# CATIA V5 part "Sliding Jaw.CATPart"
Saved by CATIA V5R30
Part number: Sliding Jaw
Bounding box of the stored display mesh (mm): x -32 to 32, y -16 to 16, z -9 to 36
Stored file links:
  D:\PROJECTS\CATIA V56R 2020\Resources\Parts File\c12_catia_v5_6r2020_prt\c12_catia_v5-6r2020 figr_12-19\Sliding Jaw.CATPart
  C:\Program Files\Dassault Systemes\B09\intel_a\reffiles\standard\MetricThickPitch.txt
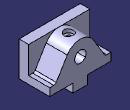
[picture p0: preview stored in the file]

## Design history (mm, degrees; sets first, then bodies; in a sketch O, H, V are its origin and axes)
Body1 (main body)
  Sketch1 on xy-plane, origin (0, 0, 0), H (1, 0, 0), V (0, 1, 0)
    line L1 (-32, -16) -> (32, -16)
    line L2 (32, -16) -> (32, 16)
    line L3 (32, 16) -> (-32, 16)
    line L4 (-32, 16) -> (-32, -16)
    distance H L1 = 16
    distance V L4 = 32
    length L4 = 32
    length L1 = 64
    horizontal: L1 H, L3 H
    vertical: L2 V, L4 V
  Pad1: profile Sketch1, direction (0, 0, 1), length 8
  Sketch2 on face of Pad1, origin (0, -16, 0), H (1, 0, 0), V (0, 0, 1)
    point P1 (-32, 0)
    line L1 (-32, 0) -> (32, 0)
    line L2 (32, 0) -> (32, 36)
    line L3 (32, 36) -> (-32, 36)
    line L4 (-32, 36) -> (-32, 0)
    reference projected line E1 (32, 0) -> (32, 8) from edge of Pad1
    reference projected line E2 (-32, 8) -> (-32, 0) from edge of Pad1
    length L2 = 36
    coincidence: P1 H, L2 E1, L4 E2
    horizontal: L1 H, L3 H
    vertical: L2 V, L4 V
  Pad2: profile Sketch2, direction (0, 1, 0), length 10
  Sketch3 on face of Pad1, origin (0, 16, 0), H (-1, 0, 0), V (0, 0, 1)
    arc A1 centre (0, 20) radius 16 from (13.6777, 28.3018) to (-13.6777, 28.3018) ccw
    point P1 (0, 20)
    reference projected line E1 (-32, 36) -> (32, 36) from edge of Pad2
    line L1 (-26, 8) -> (-13.6777, 28.3018)
    point P2 (-26, 8)
    line L2 (13.6777, 28.3018) -> (26, 8)
    point P3 (26, 8)
    reference projected line E2 (32, 8) -> (-32, 8) from edge of Pad1
    reference projected line E3 (32, 8) -> (-32, 8) from edge of Pad1
    line L3 (-26, 8) -> (26, 8)
    radius A1 = 16
    length L3 = 52
    distance V P3 = 26
    coincidence: P1 V, E2 P2, E3 P3
    tangency: A1 E1, L2 A1, L1 A1
    horizontal: L3 H
  Pad3: profile Sketch3, direction (0, -1, 0), up to the existing solid (limit type 2)
  Fillet1: radius 3, on 2 edges
  Sketch4 on face of Pad1, origin (-2.6964, 16, 22.8197), H (1, 0, 0), V (0, 0, -1)
    point P1 (2.6964, 2.8197)
    reference projected arc E1 centre (2.6964, 2.8197) radius 16 from (-10.9814, -5.4821) to (16.3741, -5.4821) ccw from edge of Pad3
    concentricity: P1 E1
  Hole1: placed by Sketch4, at (0, 16, 20) direction (0, -1, 0), diameter 12, depth 22, V-bottom angle 120
  Sketch5 on face of Pad1, origin (0, 16, 0), H (-1, 0, 0), V (0, 0, 1)
    point P1 (-7.75, 0)
    line L1 (-7.75, 0) -> (7.75, 0)
    line L2 (7.75, 0) -> (7.75, -9)
    line L3 (7.75, -9) -> (-7.75, -9)
    line L4 (-7.75, -9) -> (-7.75, 0)
    distance V L2 = 7.75
    length L3 = 15.5
    length L4 = 9
    coincidence: P1 H
    horizontal: L1 H, L3 H
    vertical: L2 V, L4 V
  Pad4: profile Sketch5, direction (0, -1, 0), length 32
  Sketch6 on face of Pad4, origin (-0.598, -1.2346, -9), H (1, 0, 0), V (0, -1, 0)
    point P1 (0.598, -9.2346)
    reference projected line E1 (8.348, -17.2346) -> (-7.152, -17.2346) from edge of Pad4
    reference projected line E2 (8.348, 14.7654) -> (8.348, -17.2346) from edge of Pad4
    distance P1 E1 = 8
    distance P1 E2 = 7.75
  Hole2: placed by Sketch6, at (0, 8, -9) direction (0, 0, 1), diameter 5, depth 16, V-bottom angle 120, threaded, thread diameter 6, thread depth 16, pitch 1
  RectPattern1: of Hole2, direction 1 instances 2, spacing 16, along edge of Pad4 reversed
  Sketch7 on face of Pad2, origin (-19.6018, -13.7351, 36), H (1, 0, 0), V (0, 1, 0)
    point P1 (19.6018, 17.7351)
    reference intersected line E1 through (19.6018, 0) direction (0, 1) from yz-plane
    reference projected line E2 (51.6018, -2.2649) -> (-12.3982, -2.2649) from edge of Pad2
    distance P1 E2 = 20
    coincidence: E1 P1
  Hole3: placed by Sketch7, at (0, 4, 36) direction (0, 0, -1), diameter 5, depth 16, V-bottom angle 120, counterbore diameter 10, counterbore depth 4, threaded, thread diameter 6, thread depth 11, pitch 1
